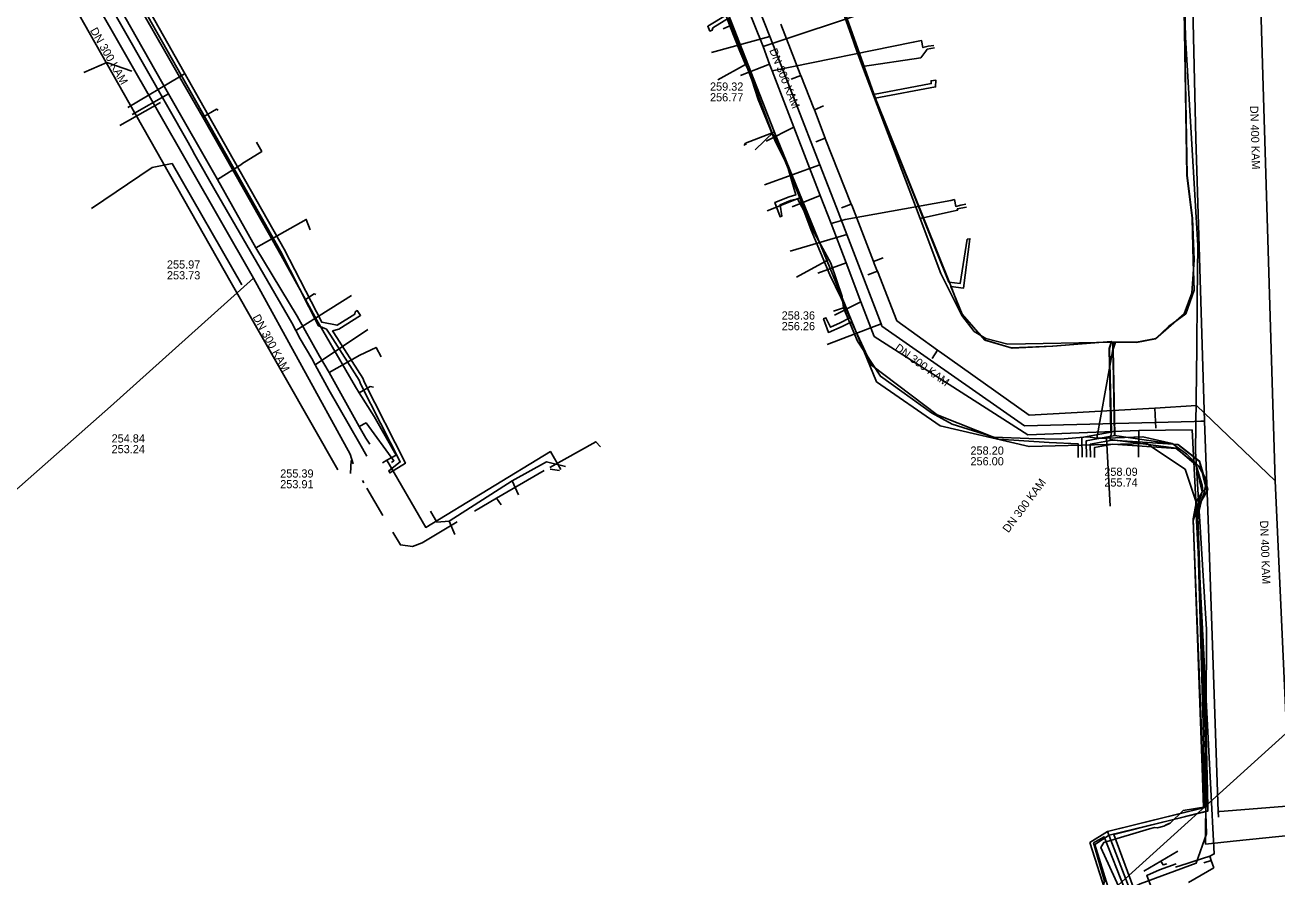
# Model space of a CAD drawing. Extents: x -598233 to -596890, y -1157848 to -1156431.
# Drawn here: x -598140.8 to -598018, y -1157081 to -1156997.4 of the extents above; entities that cross this region are included whole.
import ezdxf

# ---------------------------------------------------------------- set-up
doc = ezdxf.new("R2010")
doc.units = 0
for name, color, linetype in [('Vrstva 12', 7, 'Continuous'), ('Vrstva 13', 7, 'Continuous'), ('Vrstva 14', 7, 'Continuous'), ('Vrstva 16', 7, 'Continuous'), ('Vrstva 19', 7, 'Continuous'), ('Vrstva 42', 7, 'Continuous'), ('Vrstva 48', 7, 'Continuous'), ('Vrstva 5', 7, 'Continuous'), ('Vrstva 54', 7, 'Continuous'), ('Vrstva 55', 7, 'Continuous'), ('Vrstva 58', 7, 'Continuous'), ('Vrstva 60', 7, 'Continuous'), ('Vrstva 8', 7, 'Continuous')]:
    doc.layers.add(name, color=color, linetype=linetype)

msp = doc.modelspace()

# ---------------------------------------------------------------- linework, layer by layer
at = {"layer": 'Vrstva 12'}
for points in [[(-598081.07, -1156973.22), (-598078.12, -1156980.8), (-598074.5, -1156989.79), (-598071.67, -1156997.53)], [(-598053.06, -1156982.44), (-598053.83, -1156985.09), (-598059.81, -1156991.76), (-598061.51, -1156993.52), (-598059.76, -1156998.41)], [(-598127.08, -1157000), (-598132.78, -1156990.06), (-598134.13, -1156987.69)], [(-598071.67, -1156997.53), (-598072.32, -1156997.83)], [(-598071.67, -1156997.53), (-598070.67, -1157000)], [(-598059.76, -1156998.41), (-598059.19, -1157000)], [(-598052.44, -1157000), (-598052.3, -1156999.81), (-598051.59, -1156999.68)], [(-598125.64, -1157002.51), (-598127.08, -1157000)], [(-598070.67, -1157000), (-598070.13, -1157001.32)], [(-598059.19, -1157000), (-598058.65, -1157001.5)], [(-598058.65, -1157001.5), (-598052.94, -1157000.65), (-598052.44, -1157000)], [(-598125.16, -1157002.22), (-598125.64, -1157002.51)], [(-598070.13, -1157001.32), (-598072.84, -1157002.82)], [(-598067.54, -1157007.94), (-598068.85, -1157004.44), (-598069.71, -1157002.1), (-598070.13, -1157001.32)], [(-598052.98, -1157016.41), (-598058.65, -1157001.5)], [(-598125.64, -1157002.51), (-598130.73, -1157005.54)], [(-598123.37, -1157006.47), (-598125.64, -1157002.51)], [(-598123.37, -1157006.47), (-598122.03, -1157005.71), (-598121.86, -1157005.79)], [(-598113.28, -1157024.35), (-598115.69, -1157020.05), (-598121.46, -1157009.81), (-598123.37, -1157006.47)], [(-598067.57, -1157008.05), (-598070.12, -1157009.03)], [(-598067.57, -1157008.05), (-598067.54, -1157007.94)], [(-598067.57, -1157008.05), (-598067.47, -1157008.1), (-598067.2, -1157008.53), (-598066.08, -1157011.18), (-598064.81, -1157014.39)], [(-598070.12, -1157009.03), (-598070.26, -1157009.26)], [(-598070.12, -1157009.03), (-598070.09, -1157009.19)], [(-598064.81, -1157014.39), (-598068.01, -1157015.66)], [(-598064.81, -1157014.39), (-598064.68, -1157014.78), (-598063.56, -1157017.49), (-598061.94, -1157020.44)], [(-598052.98, -1157016.41), (-598049.92, -1157015.74), (-598049.31, -1157015.61), (-598049.35, -1157015.47), (-598048.46, -1157015.3)], [(-598035.67, -1157037.95), (-598033.97, -1157028.56), (-598044.38, -1157028.75), (-598046.54, -1157028.18), (-598047.69, -1157027.51), (-598048.89, -1157025.92), (-598050.96, -1157021.83), (-598052.98, -1157016.41)], [(-598061.94, -1157020.44), (-598065.14, -1157022.18)], [(-598061.94, -1157020.44), (-598061.75, -1157020.8), (-598060.66, -1157024.06), (-598060.5, -1157025.18)], [(-598113.28, -1157024.35), (-598112.44, -1157023.82), (-598112.29, -1157023.89)], [(-598108.01, -1157033.53), (-598108.39, -1157032.93), (-598112.17, -1157026.4), (-598113.28, -1157024.35)], [(-598061.5, -1157025.52), (-598060.5, -1157025.18)], [(-598036.56, -1157037.85), (-598039.25, -1157038.08), (-598042.35, -1157038), (-598045.78, -1157037.88), (-598049.84, -1157036.6), (-598051.89, -1157035.49), (-598056.9, -1157031.89), (-598059.13, -1157028.45), (-598060.5, -1157025.18)], [(-598108.01, -1157033.53), (-598106.93, -1157032.9), (-598106.63, -1157032.95)], [(-598108.01, -1157033.53), (-598106.56, -1157035.84), (-598104.41, -1157039.62), (-598105.3, -1157040.14)], [(-598035.67, -1157037.95), (-598036.56, -1157037.85)], [(-598034.71, -1157037.96), (-598031.15, -1157037.82), (-598028.29, -1157038.49), (-598026.83, -1157039.52), (-598025.69, -1157040.68), (-598024.89, -1157042.07), (-598025.14, -1157043.33), (-598025.92, -1157045.45), (-598025.07, -1157061.24), (-598024.76, -1157074.08), (-598027.19, -1157074.47), (-598028.47, -1157075.74)], [(-598035.67, -1157037.95), (-598034.71, -1157037.96)], [(-598034.71, -1157037.96), (-598034.36, -1157044.65)], [(-598105.3, -1157040.14), (-598105.73, -1157040.39)], [(-598088.24, -1157041.04), (-598089.27, -1157039.28), (-598101.49, -1157046.72), (-598105.3, -1157040.14)], [(-598029.1, -1157076.03), (-598028.47, -1157075.74)], [(-598028.91, -1157075.88), (-598028.47, -1157075.74)], [(-598032.98, -1157083.11), (-598035.28, -1157078.11), (-598034.99, -1157077.62), (-598030.49, -1157076.29), (-598030.01, -1157076.15)], [(-598030.01, -1157076.15), (-598029.72, -1157076.17)], [(-598029.72, -1157076.17), (-598029.1, -1157076.03)]]:
    msp.add_lwpolyline(points, dxfattribs=at)
at = {"layer": 'Vrstva 13'}
for p, q in [((-598067.75, -1156998.56), (-598073.45, -1157000.14)), ((-598127.5, -1157005.03), (-598131.51, -1157007.31)), ((-598062.82, -1157011.17), (-598068.27, -1157013.11)), ((-598060.19, -1157017.99), (-598065.73, -1157019.61)), ((-598114.25, -1157027.39), (-598108.79, -1157023.97)), ((-598056.83, -1157026.76), (-598062.13, -1157028.77)), ((-598112.33, -1157030.78), (-598107.16, -1157027.3)), ((-598025.09, -1157036.31), (-598025.45, -1157036.31)), ((-598023.75, -1157074.57), (-598023.6, -1157074.57)), ((-598023.73, -1157075.13), (-598023.75, -1157074.57))]:
    msp.add_line(p, q, dxfattribs=at)
for points in [[(-598025.45, -1157036.31), (-598026.1, -1157036.32), (-598042.77, -1157036.77), (-598056.75, -1157026.97), (-598056.83, -1157026.76), (-598060.19, -1157017.99), (-598061.19, -1157015.34), (-598062.82, -1157011.17), (-598065.22, -1157005.02), (-598067.75, -1156998.56), (-598069.4, -1156994.32), (-598076.91, -1156975.08), (-598080, -1156967.15), (-598080.47, -1156965.95), (-598082.95, -1156959.54), (-598083.71, -1156957.56), (-598085.45, -1156953.05), (-598087.93, -1156946.58), (-598088.89, -1156944.11), (-598097, -1156923.19)], [(-598025.09, -1157036.31), (-598025.78, -1157013.84), (-598025.94, -1157008.58), (-598026.2, -1156997.2), (-598026.43, -1156987.34), (-598026.69, -1156975.55), (-598026.83, -1156969.58), (-598026.95, -1156964.54), (-598027.01, -1156959.7), (-598026.85, -1156958.67)], [(-598135.28, -1156990.52), (-598124.79, -1157008.96), (-598124.43, -1157009.61), (-598124.13, -1157010.16), (-598122.16, -1157013.67), (-598114.64, -1157026.67), (-598114.25, -1157027.39), (-598113.8, -1157028.22), (-598112.67, -1157030.15), (-598112.33, -1157030.78), (-598110.99, -1157033.23), (-598107.97, -1157038.52), (-598107.28, -1157039.74)], [(-598023.75, -1157074.57), (-598024.69, -1157047.73), (-598025.09, -1157036.31)], [(-598101.04, -1157045.11), (-598100.39, -1157046.19), (-598099.18, -1157046.1), (-598093, -1157042.16), (-598089.64, -1157040.3), (-598087.78, -1157040.75)], [(-598093, -1157042.16), (-598092.41, -1157043.51)], [(-598099.18, -1157046.1), (-598098.63, -1157047.4)], [(-598015.03, -1157080.86), (-598015.59, -1157076.4), (-598015.7, -1157074.89), (-598016.63, -1157074.02), (-598023.6, -1157074.57)]]:
    msp.add_lwpolyline(points, dxfattribs=at)
at = {"layer": 'Vrstva 14'}
msp.add_lwpolyline([(-598114.89, -1157120.49), (-598037.32, -1157085.21), (-598015.06, -1157065.07)], dxfattribs=at)
at = {"layer": 'Vrstva 16'}
for points in [[(-598068.41, -1156999.56), (-598057.48, -1156995.92), (-598055.69, -1156983.37), (-598055.25, -1156980.32), (-598054.5, -1156975.1), (-598052.84, -1156964.29), (-598051.07, -1156952.84), (-598048, -1156932.45), (-598045.86, -1156918.24), (-598045.71, -1156917.22)], [(-598098.27, -1156924.44), (-598101.61, -1156925.86), (-598114.81, -1156931.12), (-598117.84, -1156933.14), (-598122.21, -1156937.79), (-598125.38, -1156942.42), (-598127.58, -1156950.25), (-598129.31, -1156956.4), (-598135.89, -1156981.17), (-598137.09, -1156985.7), (-598134.79, -1156989.9), (-598133.51, -1156992.23), (-598126.72, -1157004.19), (-598121.93, -1157012.6), (-598118.17, -1157019.31), (-598114.11, -1157026.01), (-598111.9, -1157029.92), (-598110.97, -1157031.54), (-598108.01, -1157036.82), (-598107.36, -1157037.95), (-598106.99, -1157038.54)], [(-598070.09, -1156995.32), (-598068.41, -1156999.56), (-598067.76, -1157001.27), (-598067.5, -1157001.93), (-598065.38, -1157007.46), (-598062.8, -1157014.17), (-598061.74, -1157016.9), (-598060.26, -1157020.77), (-598058.81, -1157024.61), (-598057.49, -1157027.98), (-598042.43, -1157037.63), (-598031.55, -1157037.21), (-598026.32, -1157037.16)], [(-598067.5, -1157001.93), (-598053.67, -1156999.14), (-598052.86, -1156998.97), (-598052.72, -1156999.66), (-598052.2, -1156999.53), (-598051.64, -1156999.44)], [(-598067.76, -1157001.27), (-598070.61, -1157002.38)], [(-598126.72, -1157004.19), (-598130.28, -1157006.21)], [(-598065.38, -1157007.46), (-598068.09, -1157008.82)], [(-598121.93, -1157012.6), (-598119.53, -1157011.08), (-598119.52, -1157011.07), (-598117.58, -1157009.84), (-598118.08, -1157008.95)], [(-598062.8, -1157014.17), (-598065.56, -1157015.29)], [(-598061.74, -1157016.9), (-598060.36, -1157016.51), (-598049.98, -1157014.64), (-598049.63, -1157014.57), (-598049.5, -1157015.23), (-598049.02, -1157015.12), (-598048.52, -1157015.02)], [(-598118.17, -1157019.31), (-598113.22, -1157016.51), (-598112.82, -1157017.53)], [(-598060.26, -1157020.77), (-598063.02, -1157021.79)], [(-598058.81, -1157024.61), (-598061.41, -1157025.91)], [(-598110.97, -1157031.54), (-598107.96, -1157029.84), (-598106.37, -1157029.07), (-598105.86, -1157029.98)], [(-598108.01, -1157036.82), (-598107.35, -1157036.47), (-598104.61, -1157040.18), (-598104.84, -1157040.34)], [(-598031.55, -1157037.21), (-598031.56, -1157039.83)], [(-598024.2, -1157080.12), (-598024.45, -1157079.38), (-598024.59, -1157078.95), (-598024.14, -1157078.74), (-598026.32, -1157037.16)], [(-598024.59, -1157078.95), (-598026.12, -1157079.44), (-598026.8, -1157079.7), (-598027.94, -1157080.05)], [(-598024.45, -1157079.38), (-598025.16, -1157079.61)], [(-598026.68, -1157081.55), (-598024.2, -1157080.12)]]:
    msp.add_lwpolyline(points, dxfattribs=at)
at = {"layer": 'Vrstva 19'}
msp.add_lwpolyline([(-598027.48, -1157088.69), (-598027.74, -1157088.05), (-598027.94, -1157088.17), (-598030.77, -1157080.85), (-598029.5, -1157080.31), (-598027.89, -1157079.73)], dxfattribs=at)
at = {"layer": 'Vrstva 42'}
for points in [[(-598111.23, -1157027.27), (-598112, -1157026.94), (-598115.74, -1157019.62), (-598121.15, -1157010.05), (-598134.49, -1156986.43)], [(-598134.06, -1156986.38), (-598120.8, -1157009.85), (-598115.39, -1157019.43), (-598111.69, -1157026.59), (-598110.19, -1157026.89), (-598108.45, -1157025.81), (-598108.43, -1157025.59), (-598108.22, -1157025.45), (-598107.89, -1157025.93), (-598110.03, -1157027.26), (-598110.64, -1157027.44)], [(-598037.09, -1157039.84), (-598037.12, -1157037.9), (-598034.3, -1157037.38), (-598034.47, -1157029.17), (-598034.22, -1157028.47), (-598040.01, -1157028.93), (-598044.06, -1157029.11), (-598046.64, -1157028.35), (-598048.87, -1157025.81), (-598050, -1157023.09), (-598048.74, -1157023.24), (-598048.12, -1157018.41), (-598048.37, -1157018.46), (-598049.08, -1157022.8), (-598050.18, -1157022.67), (-598051.47, -1157019.49), (-598057.42, -1157004.63), (-598051.48, -1157003.51), (-598051.46, -1157002.85), (-598051.92, -1157002.91), (-598051.9, -1157003.19), (-598057.57, -1157004.25), (-598061.46, -1156993.43)], [(-598036.69, -1157039.83), (-598036.71, -1157038.23), (-598033.89, -1157037.71), (-598034.07, -1157029.23), (-598033.82, -1157028.54), (-598031.76, -1157028.58), (-598029.91, -1157028.23), (-598027.1, -1157025.76), (-598026.33, -1157023.73), (-598026.13, -1157020.49), (-598026.27, -1157016.42), (-598026.8, -1157012.17), (-598027.06, -1156997.54), (-598027.04, -1156993.49)], [(-598071.93, -1156996.4), (-598073.83, -1156997.56), (-598073.62, -1156998.04), (-598073.4, -1156997.95), (-598073.33, -1156997.72), (-598071.79, -1156996.78), (-598069.52, -1157002.82), (-598068.87, -1157004.76), (-598067.17, -1157008.91), (-598066.05, -1157011.18), (-598065.2, -1157014.11), (-598065.83, -1157014.28), (-598067.24, -1157014.85), (-598066.74, -1157016.25), (-598066.55, -1157016.18), (-598066.73, -1157015.08), (-598065.71, -1157014.66), (-598065.04, -1157014.48), (-598064.41, -1157015.64), (-598063.67, -1157017.57), (-598061.84, -1157021.94), (-598060.75, -1157024.24), (-598059.88, -1157026.18), (-598060.83, -1157026.64), (-598061.8, -1157027.08), (-598062.24, -1157026.16), (-598062.47, -1157026.26), (-598061.99, -1157027.6), (-598060.66, -1157027), (-598059.72, -1157026.54), (-598057.78, -1157030.82), (-598051.31, -1157035.67), (-598045.31, -1157038.08), (-598040.34, -1157038.39), (-598037.51, -1157038.52), (-598037.49, -1157039.87)], [(-598110.64, -1157027.44), (-598110.51, -1157027.64), (-598107.68, -1157032.08), (-598107.49, -1157032.52), (-598103.48, -1157040.42), (-598105.01, -1157041.37), (-598105.13, -1157041.16), (-598103.99, -1157040.3), (-598107.85, -1157032.69), (-598108.03, -1157032.27), (-598110.85, -1157027.86), (-598111.23, -1157027.27)], [(-598034.98, -1157082.31), (-598034.89, -1157082.25), (-598036.34, -1157077.63), (-598034.61, -1157076.54), (-598025.19, -1157074.23), (-598025.32, -1157070.27), (-598026.2, -1157045.87), (-598025.88, -1157044.14), (-598025.28, -1157043.15), (-598025.33, -1157042.59), (-598025.54, -1157041.96), (-598025.96, -1157040.49), (-598027.87, -1157038.97), (-598034.09, -1157038.56), (-598035.9, -1157038.89), (-598035.89, -1157039.85)], [(-598034.82, -1157082.58), (-598034.46, -1157082.36), (-598035.86, -1157077.81), (-598034.45, -1157076.92), (-598024.78, -1157074.55), (-598024.92, -1157070.25), (-598025.8, -1157045.91), (-598025.5, -1157044.28), (-598024.86, -1157043.21), (-598025.6, -1157040.27), (-598027.71, -1157038.59), (-598034.16, -1157038.17), (-598036.31, -1157038.56), (-598036.29, -1157039.83)]]:
    msp.add_lwpolyline(points, dxfattribs=at)
at = {"layer": 'Vrstva 48'}
for points in [[(-598031.05, -1157080.42), (-598029.39, -1157079.46), (-598027.71, -1157078.49)], [(-598029.39, -1157079.46), (-598029.17, -1157079.83), (-598028.81, -1157079.72)]]:
    msp.add_lwpolyline(points, dxfattribs=at)
at = {"layer": 'Vrstva 5'}
for p, q in [((-598020.81, -1156957.8), (-598019.37, -1157002.35)), ((-598139.18, -1156985.92), (-598118.38, -1157022.27)), ((-598065.64, -1157002.76), (-598064.71, -1157002.39)), ((-598019.37, -1157002.35), (-598018.16, -1157042.14)), ((-598062.46, -1157005.38), (-598063.37, -1157005.75)), ((-598063.23, -1157008.9), (-598062.32, -1157008.54)), ((-598126.36, -1157011.03), (-598119.53, -1157022.92)), ((-598060.7, -1157015.37), (-598059.75, -1157015.01)), ((-598056.63, -1157020.28), (-598057.58, -1157020.65)), ((-598058.13, -1157021.94), (-598057.19, -1157021.58)), ((-598118.38, -1157022.27), (-598132.42, -1157034.86)), ((-598108.9, -1157039.54), (-598118.38, -1157022.27)), ((-598051.83, -1157030.15), (-598051.29, -1157029.35)), ((-598132.42, -1157034.86), (-598169.28, -1157067.35)), ((-598029.87, -1157037), (-598029.99, -1157035.01)), ((-598025.9, -1157034.77), (-598018.16, -1157042.14)), ((-598108.8, -1157040.15), (-598108.86, -1157041.42)), ((-598089.3, -1157041.02), (-598088.37, -1157041.15)), ((-598094.54, -1157043.85), (-598094.08, -1157044.49))]:
    msp.add_line(p, q, dxfattribs=at)
for points in [[(-598066.67, -1156997.36), (-598064.75, -1157002.27), (-598064.71, -1157002.39), (-598063.42, -1157005.62), (-598063.37, -1157005.75), (-598062.32, -1157008.54), (-598062.31, -1157008.56), (-598059.75, -1157015.01), (-598059.71, -1157015.11), (-598057.58, -1157020.65), (-598057.51, -1157020.83), (-598057.23, -1157021.5), (-598057.19, -1157021.58), (-598055.29, -1157026.46)], [(-598135.04, -1157002.09), (-598132.79, -1157001.13), (-598130.33, -1157001.97)], [(-598134.28, -1157015.44), (-598128.32, -1157011.42), (-598126.36, -1157011.03)], [(-598055.29, -1157026.46), (-598051.29, -1157029.35), (-598051.11, -1157029.47), (-598042.29, -1157035.71)], [(-598042.29, -1157035.71), (-598029.99, -1157035.01), (-598025.9, -1157034.77)], [(-598084.35, -1157038.8), (-598084.8, -1157038.32), (-598089.33, -1157040.83)], [(-598108.9, -1157039.54), (-598108.6, -1157040.5)], [(-598096.7, -1157045.14), (-598094.54, -1157043.85), (-598089.88, -1157041.14)], [(-598107.69, -1157042.13), (-598107.57, -1157042.34)], [(-598018.16, -1157042.14), (-598017.2, -1157063.68), (-598016.4, -1157081.82)], [(-598107.27, -1157042.87), (-598105.7, -1157045.54)], [(-598104.71, -1157047.2), (-598103.98, -1157048.44), (-598102.79, -1157048.6), (-598101.86, -1157048.23), (-598098.41, -1157046.17)]]:
    msp.add_lwpolyline(points, dxfattribs=at)
at = {"layer": 'Vrstva 54'}
for p, q in [((-598027.67, -1156974.53), (-598026.95, -1156998.63)), ((-598026.95, -1156998.63), (-598025.75, -1157019.06)), ((-598025.75, -1157019.06), (-598025.81, -1157024.28)), ((-598025.81, -1157024.28), (-598025.87, -1157029.09)), ((-598025.87, -1157029.09), (-598026, -1157039.23)), ((-598026, -1157039.23), (-598025.69, -1157044.06)), ((-598025.69, -1157044.06), (-598024.89, -1157056.73)), ((-598024.89, -1157056.73), (-598024.97, -1157072.7)), ((-598024.97, -1157072.7), (-598025, -1157077.78)), ((-598022.29, -1157077.5), (-598016.22, -1157076.88)), ((-598025, -1157077.78), (-598022.29, -1157077.5))]:
    msp.add_line(p, q, dxfattribs=at)
at = {"layer": 'Vrstva 55'}
for points in [[(-598027.28, -1156983.86), (-598026.84, -1157012.18), (-598026.3, -1157016.4), (-598026.21, -1157020.62), (-598026.12, -1157023.44), (-598026.93, -1157025.77), (-598028.63, -1157027.03), (-598029.89, -1157028.2), (-598031.77, -1157028.56), (-598034.11, -1157028.56), (-598033.93, -1157037.71), (-598027.64, -1157038.61), (-598025.58, -1157040.23), (-598024.77, -1157043.01), (-598025.4, -1157044.09), (-598025.76, -1157045.61), (-598024.76, -1157074.52), (-598033.98, -1157076.83), (-598032.11, -1157081.97), (-598032.31, -1157082.14)], [(-598139.81, -1156988.8), (-598130.63, -1157005.04), (-598120.58, -1157022.74), (-598110.12, -1157041.06)], [(-598032.31, -1157082.14), (-598032.49, -1157082.06), (-598034.61, -1157076.54), (-598025.09, -1157074.18), (-598026.2, -1157046.04), (-598025.33, -1157043.23), (-598025.96, -1157040.59), (-598027.88, -1157038.96), (-598034.37, -1157038.09), (-598034.22, -1157037.42), (-598034.42, -1157029.18), (-598034.22, -1157028.5), (-598039.99, -1157028.94), (-598043.98, -1157029.13), (-598046.57, -1157028.36), (-598048.93, -1157025.76), (-598049.99, -1157023.02), (-598057.39, -1157004.64), (-598061.38, -1156993.42)], [(-598088.45, -1157117.6), (-598060.82, -1157104.83), (-598032.04, -1157091.03), (-598033.2, -1157090.72), (-598036.26, -1157086.54), (-598036.44, -1157084.93), (-598035.54, -1157083.67), (-598034.91, -1157081.43), (-598035.99, -1157077.66), (-598034.94, -1157077.07), (-598032.88, -1157082.31), (-598032.31, -1157082.14)]]:
    msp.add_lwpolyline(points, dxfattribs=at)
at = {"layer": 'Vrstva 58'}
for points in [[(-598067.3, -1157007.88), (-598076.04, -1156985.52), (-598085.14, -1156962.29)], [(-598122.13, -1157128.47), (-598120.88, -1157127.19), (-598119.85, -1157126.19), (-598114.45, -1157121.65), (-598113.95, -1157121.4), (-598104.88, -1157116.49), (-598095.85, -1157111.99), (-598056.77, -1157094.01), (-598031.41, -1157081.68), (-598025.91, -1157079.65), (-598024.92, -1157076.77), (-598025.03, -1157072.78), (-598025.86, -1157044.43), (-598027, -1157041.02), (-598030.8, -1157038.5), (-598042.31, -1157038.79), (-598051.03, -1157036.76), (-598057.28, -1157032.44), (-598067.3, -1157007.88)], [(-598067.3, -1157007.88), (-598069.18, -1157009.69)]]:
    msp.add_lwpolyline(points, dxfattribs=at)
at = {"layer": 'Vrstva 60'}
for points in [[(-598027.67, -1156974.53), (-598026.95, -1156998.63), (-598025.75, -1157019.06), (-598025.81, -1157024.28), (-598025.87, -1157029.09), (-598026, -1157039.23), (-598025.69, -1157044.06), (-598024.89, -1157056.73), (-598024.97, -1157072.7), (-598025, -1157077.78), (-598022.29, -1157077.5), (-598016.22, -1157076.88)], [(-598016.22, -1157076.88), (-598022.29, -1157077.5), (-598025, -1157077.78), (-598024.97, -1157072.7), (-598024.89, -1157056.73), (-598025.69, -1157044.06), (-598026, -1157039.23), (-598025.87, -1157029.09), (-598025.81, -1157024.28), (-598025.75, -1157019.06), (-598026.95, -1156998.63), (-598027.67, -1156974.53)]]:
    msp.add_lwpolyline(points, dxfattribs=at)

# ---------------------------------------------------------------- texts
at = {"layer": 'Vrstva 8'}
for s, rotation, p in [('DN 300 KAM', 299.7715, (-598134.45, -1156997.97)), ('DN 300 KAM', 291.6355, (-598067.81, -1156999.92)), ('DN 400 KAM', 271.7539, (-598020.63, -1157005.38)), ('DN 300 KAM', 298.7402, (-598118.5, -1157026.09)), ('DN 300 KAM', 324.222, (-598055.56, -1157029.28)), ('DN 300 KAM', 53.2851, (-598044.34, -1157047.31)), ('DN 400 KAM', 272.1537, (-598019.66, -1157046.06))]:
    msp.add_text(s, height=0.8, rotation=rotation, dxfattribs=at).set_placement(p)
for s, p in [('259.32', (-598073.61, -1157003.88)), ('256.77', (-598073.61, -1157004.93)), ('255.97', (-598126.88, -1157021.33)), ('253.73', (-598126.88, -1157022.39)), ('258.36', (-598066.58, -1157026.33)), ('256.26', (-598066.58, -1157027.38)), ('254.84', (-598132.31, -1157038.39)), ('253.24', (-598132.31, -1157039.44)), ('258.20', (-598048.06, -1157039.58)), ('256.00', (-598048.06, -1157040.63)), ('255.39', (-598115.77, -1157041.83)), ('258.09', (-598034.93, -1157041.66)), ('253.91', (-598115.77, -1157042.88)), ('255.74', (-598034.93, -1157042.71))]:
    msp.add_text(s, height=0.8, dxfattribs=at).set_placement(p)

doc.saveas('drawing.dxf')
